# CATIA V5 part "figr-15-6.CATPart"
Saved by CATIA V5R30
Part number: Part1
Bounding box of the stored display mesh (mm): x -50 to 50, y -32.5 to 33.5, z -52 to 1
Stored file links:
  D:\PROJECTS\CATIA V56R 2020\Resources\Parts File\c15_catia_v5_6r2020_prt\figr-15-6.CATPart
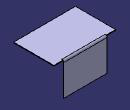
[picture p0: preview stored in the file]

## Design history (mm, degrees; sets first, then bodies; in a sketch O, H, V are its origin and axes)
SheetMetalParameters1: Thickness 1, BendRadius 2, KFactor 0.400515 {= log(min(100,max(20*SheetMetalParameters1.BendRadius,SheetMetalParameters1.Thickness)/SheetMetalParameters1.Thickness))/log(100)/2}, ReliefRadialLength 1, ReliefAxialLength 2, MinimumBendRadius 0
Body1 (main body)
  Sketch1 on xy-plane, origin (0, 0, 0), H (1, 0, 0), V (0, 1, 0)
    line L1 (-50, 32.5) -> (50, 32.5)
    line L2 (50, 32.5) -> (50, -32.5)
    line L3 (50, -32.5) -> (-50, -32.5)
    line L4 (-50, -32.5) -> (-50, 32.5)
    length L1 = 100
    length L2 = 65
    horizontal: L1 H, L3 H
    vertical: L2 V, L4 V
    symmetry: L4 L2 V, L1 L3 H
  Wall1: Thickness 1, Profile Sketch1
  d_NewWallOnEdge1: NewWallOnEdge_Edge edge [face of Wall1 | face of Wall1], NewWallOnEdge_Length 53, NewWallOnEdge_HeightLimitOffset 0, NewWallOnEdge_WidthOffset1 -15, NewWallOnEdge_WidthOffset2 -15, NewWallOnEdge_Angle 90, NewWallOnEdge_BendRadiusValue 2 {= SheetMetalParameters1.BendRadius}, NewWallOnEdge_BendTable SheetMetalParameters1, KFacteur 0.400515 {= log(min(100,max(20*d_NewWallOnEdge1.Radius,SheetMetalParameters1.Thickness)/SheetMetalParameters1.Thickness))/log(100)/2}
